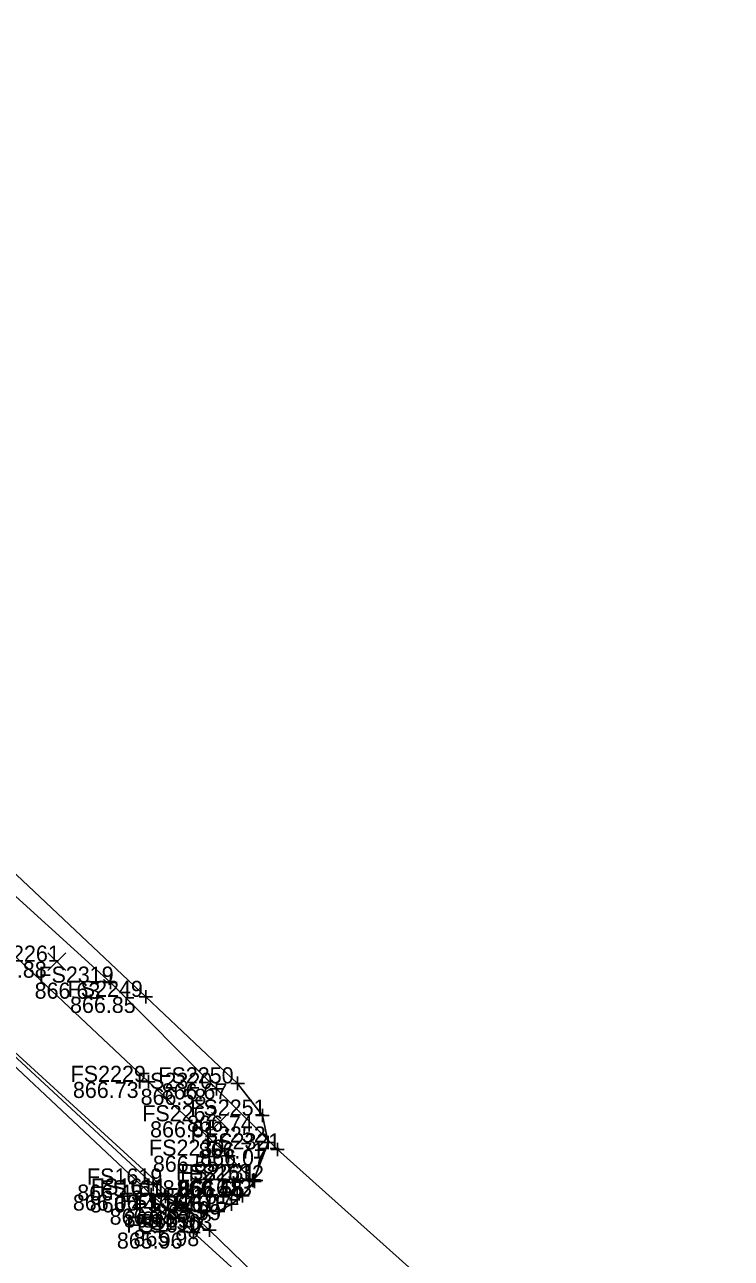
# Model space of a CAD drawing. Extents: x 1479420 to 1479833, y 379731 to 380103.
# Drawn here: x 1479766 to 1479818.8, y 379820.1 to 379912.2 of the extents above; entities that cross this region are included whole.
import ezdxf

# ---------------------------------------------------------------- set-up
doc = ezdxf.new("R2010")
doc.units = 0
for name, color, linetype in [('PV_X_Curb', 7, 'Continuous'), ('PV_X_Walk', 7, 'Continuous'), ('SV_X_Random_Point', 7, 'Continuous'), ('SV_X_Shot_Marker', 7, 'Continuous'), ('SV_X_Text_Elevation', 7, 'Continuous'), ('SV_X_Text_Name', 7, 'Continuous'), ('UT_X_Gas', 7, 'Continuous'), ('UT_X_Water', 7, 'Continuous')]:
    doc.layers.add(name, color=color, linetype=linetype)

msp = doc.modelspace()

# ---------------------------------------------------------------- linework, layer by layer
at = {"layer": 'PV_X_Curb'}
for points in [[(1479714.573, 379931.716), (1479714.771, 379922.599), (1479714.229, 379900.013), (1479714.491, 379898.192), (1479715.218, 379896.002), (1479717.036, 379893.796), (1479731.944, 379880.013), (1479745.709, 379867.308), (1479763.187, 379850.751), (1479775.061, 379839.578), (1479781.928, 379833.121), (1479783.777, 379830.713), (1479784.214, 379828.705), (1479783.141, 379825.906)], [(1479818.811, 379784.125), (1479817.439, 379785.583), (1479804.233, 379798.167), (1479791.741, 379810.033), (1479778.638, 379821.983), (1479775.464, 379824.819), (1479758.378, 379840.845), (1479740.8, 379857.042), (1479740.592, 379857.626), (1479737.808, 379860.038), (1479735.87, 379861.852), (1479733.787, 379863.763), (1479718.701, 379877.898), (1479705.478, 379890.334), (1479700.95, 379894.575), (1479699.048, 379897.264), (1479697.778, 379899.5), (1479696.445, 379902.732), (1479695.776, 379905.397), (1479695.475, 379907.419), (1479695.142, 379911.53), (1479695.083, 379915.321)], [(1479783.191, 379825.805), (1479782.298, 379824.723), (1479781.461, 379824.102), (1479780.469, 379823.552), (1479779.204, 379823.559), (1479778.041, 379823.771), (1479776.54, 379824.685), (1479775.613, 379825.569), (1479758.651, 379841.237), (1479741.143, 379857.755), (1479738.162, 379860.576), (1479738.292, 379860.892), (1479733.926, 379864.875), (1479733.77, 379864.743), (1479718.903, 379878.446), (1479705.833, 379890.72), (1479701.383, 379894.844), (1479699.526, 379897.551), (1479698.177, 379899.762), (1479696.913, 379902.812), (1479696.188, 379905.546), (1479696.149, 379907.481), (1479695.686, 379911.644), (1479695.62, 379915.117)]]:
    msp.add_lwpolyline(points, dxfattribs=at)
at = {"layer": 'PV_X_Walk'}
msp.add_lwpolyline([(1479714.407, 379931.65), (1479709.589, 379929.394), (1479706.362, 379927.006), (1479703.827, 379924.359), (1479702.38, 379922.179), (1479701.604, 379920.676), (1479701.232, 379918.285), (1479701.216, 379916.698), (1479701.871, 379912.679), (1479703.861, 379906.887), (1479705.425, 379903.147), (1479707.313, 379899.269), (1479709.707, 379895.256), (1479713.76, 379890.533), (1479726.083, 379878.959), (1479737.973, 379867.989), (1479746.242, 379860.487), (1479749.391, 379863.573), (1479751.936, 379861.299), (1479749.037, 379858.043), (1479762.483, 379845.218), (1479775.26, 379833.23), (1479781.252, 379827.717), (1479783.036, 379825.875)], dxfattribs=at)
at = {"layer": 'SV_X_Random_Point'}
for p, q in [((1479767.756, 379841.539), (1479769.09, 379842.874)), ((1479767.756, 379842.874), (1479769.09, 379841.539)), ((1479779.963, 379829.621), (1479781.297, 379830.956)), ((1479779.963, 379830.956), (1479781.297, 379829.621))]:
    msp.add_line(p, q, dxfattribs=at)
at = {"layer": 'SV_X_Shot_Marker'}
for p, q in [((1479771.936, 379840.641), (1479772.936, 379840.641)), ((1479772.436, 379841.141), (1479772.436, 379840.141)), ((1479772.436, 379840.641), (1479772.436, 379840.641)), ((1479774.561, 379839.578), (1479775.561, 379839.578)), ((1479775.061, 379840.078), (1479775.061, 379839.078)), ((1479775.061, 379839.578), (1479775.061, 379839.578)), ((1479774.76, 379833.23), (1479775.76, 379833.23)), ((1479775.26, 379833.73), (1479775.26, 379832.73)), ((1479775.26, 379833.23), (1479775.26, 379833.23)), ((1479780.346, 379833.215), (1479780.346, 379832.215)), ((1479781.428, 379833.121), (1479782.428, 379833.121)), ((1479781.928, 379833.621), (1479781.928, 379832.621)), ((1479781.928, 379833.121), (1479781.928, 379833.121)), ((1479779.846, 379832.715), (1479780.846, 379832.715)), ((1479780.346, 379832.715), (1479780.346, 379832.715)), ((1479783.777, 379831.213), (1479783.777, 379830.213)), ((1479783.277, 379830.713), (1479784.277, 379830.713)), ((1479783.777, 379830.713), (1479783.777, 379830.713)), ((1479783.714, 379828.705), (1479784.714, 379828.705)), ((1479784.214, 379829.205), (1479784.214, 379828.205)), ((1479784.214, 379828.705), (1479784.214, 379828.705)), ((1479784.901, 379828.691), (1479784.901, 379827.691)), ((1479780.752, 379827.717), (1479781.752, 379827.717)), ((1479781.252, 379828.217), (1479781.252, 379827.217)), ((1479781.252, 379827.717), (1479781.252, 379827.717)), ((1479784.401, 379828.191), (1479785.401, 379828.191)), ((1479784.901, 379828.191), (1479784.901, 379828.191)), ((1479775.613, 379826.069), (1479775.613, 379825.069)), ((1479782.536, 379825.875), (1479783.536, 379825.875)), ((1479782.641, 379825.906), (1479783.641, 379825.906)), ((1479782.691, 379825.805), (1479783.691, 379825.805)), ((1479783.036, 379826.375), (1479783.036, 379825.375)), ((1479783.036, 379825.875), (1479783.036, 379825.875)), ((1479783.141, 379826.406), (1479783.141, 379825.406)), ((1479783.141, 379825.906), (1479783.141, 379825.906)), ((1479783.191, 379826.305), (1479783.191, 379825.305)), ((1479783.191, 379825.805), (1479783.191, 379825.805)), ((1479774.964, 379824.819), (1479775.964, 379824.819)), ((1479775.113, 379825.569), (1479776.113, 379825.569)), ((1479775.464, 379825.319), (1479775.464, 379824.319)), ((1479775.464, 379824.819), (1479775.464, 379824.819)), ((1479775.613, 379825.569), (1479775.613, 379825.569)), ((1479776.54, 379825.185), (1479776.54, 379824.185)), ((1479782.298, 379825.223), (1479782.298, 379824.223)), ((1479776.04, 379824.685), (1479777.04, 379824.685)), ((1479776.54, 379824.685), (1479776.54, 379824.685)), ((1479778.041, 379824.271), (1479778.041, 379823.271)), ((1479779.204, 379824.059), (1479779.204, 379823.059)), ((1479780.469, 379824.052), (1479780.469, 379823.052)), ((1479780.961, 379824.102), (1479781.961, 379824.102)), ((1479781.461, 379824.602), (1479781.461, 379823.602)), ((1479781.461, 379824.102), (1479781.461, 379824.102)), ((1479781.798, 379824.723), (1479782.798, 379824.723)), ((1479782.298, 379824.723), (1479782.298, 379824.723)), ((1479777.541, 379823.771), (1479778.541, 379823.771)), ((1479778.041, 379823.771), (1479778.041, 379823.771)), ((1479778.704, 379823.559), (1479779.704, 379823.559)), ((1479779.204, 379823.559), (1479779.204, 379823.559)), ((1479779.969, 379823.552), (1479780.969, 379823.552)), ((1479780.469, 379823.552), (1479780.469, 379823.552)), ((1479778.138, 379821.983), (1479779.138, 379821.983)), ((1479778.638, 379822.483), (1479778.638, 379821.483)), ((1479778.638, 379821.983), (1479778.638, 379821.983)), ((1479779.315, 379822.167), (1479780.315, 379822.167)), ((1479779.815, 379822.667), (1479779.815, 379821.667)), ((1479779.815, 379822.167), (1479779.815, 379822.167))]:
    msp.add_line(p, q, dxfattribs=at)
at = {"layer": 'UT_X_Gas'}
msp.add_lwpolyline([(1479667.444, 379946.572), (1479666.862, 379942.802), (1479667.538, 379940.507), (1479675.403, 379934.504), (1479682.743, 379926.326), (1479692.421, 379916.824), (1479702.659, 379906.694), (1479713.881, 379895.567), (1479724.225, 379885.781), (1479733.117, 379877.795), (1479742.697, 379869.326), (1479754.816, 379857.131), (1479762.869, 379849.318), (1479772.436, 379840.641), (1479780.346, 379832.715), (1479784.901, 379828.191), (1479795.906, 379818.324), (1479806.128, 379806.719), (1479816.671, 379794.927)], dxfattribs=at)
at = {"layer": 'UT_X_Water'}
msp.add_lwpolyline([(1479682.752, 379913.809), (1479688.353, 379908.314), (1479695.924, 379900.161), (1479705.441, 379891.596), (1479719.261, 379878.171), (1479726.79, 379870.913), (1479729.608, 379870.544), (1479735.551, 379869.684), (1479739.947, 379866.49), (1479744.65, 379861.847), (1479745.833, 379856.023), (1479753.929, 379847.124), (1479764.701, 379835.97), (1479779.815, 379822.167), (1479798.248, 379804.283), (1479815.468, 379787.444)], dxfattribs=at)

# ---------------------------------------------------------------- texts
at = {"layer": 'SV_X_Text_Elevation'}
for s, p in [('866.88', (1479762.754, 379841.007)), ('866.63', (1479766.758, 379839.441)), ('866.85', (1479769.402, 379838.378)), ('866.73', (1479769.619, 379832.03)), ('866.67', (1479776.25, 379831.921)), ('866.58', (1479774.677, 379831.515)), ('866.61', (1479775.385, 379829.089)), ('866.74', (1479778.146, 379829.513)), ('866.71', (1479779.007, 379827.505)), ('866.55', (1479775.593, 379826.517)), ('866.07', (1479779.128, 379826.991)), ('866.48', (1479777.358, 379824.675)), ('866.55', (1479777.482, 379824.706)), ('866.55', (1479777.532, 379824.605)), ('866.06', (1479769.616, 379823.619)), ('866.45', (1479769.944, 379824.369)), ('866.07', (1479776.525, 379823.523)), ('866.44', (1479770.881, 379823.485)), ('865.99', (1479775.792, 379822.902)), ('866.35', (1479772.363, 379822.571)), ('866.09', (1479773.422, 379822.359)), ('865.97', (1479774.81, 379822.352)), ('865.96', (1479772.903, 379820.783)), ('865.98', (1479774.146, 379820.967))]:
    msp.add_text(s, height=1.2, dxfattribs=at).set_placement(p)
at = {"layer": 'SV_X_Text_Name'}
for s, p in [('FS2261', (1479763.018, 379842.207)), ('FS2319', (1479767.042, 379840.641)), ('FS2249', (1479769.222, 379839.578)), ('FS2229', (1479769.449, 379833.23)), ('FS2250', (1479776.004, 379833.121)), ('FS2320', (1479774.403, 379832.715)), ('FS2262', (1479774.801, 379830.289)), ('FS2251', (1479778.391, 379830.713)), ('FS2252', (1479778.403, 379828.705)), ('FS2321', (1479779.496, 379828.191)), ('FS2230', (1479775.309, 379827.717)), ('FS1619', (1479770.673, 379825.569)), ('FS2253', (1479777.321, 379825.906)), ('FS2231', (1479777.631, 379825.875)), ('FS1612', (1479778.27, 379825.805)), ('FS1611', (1479770.967, 379824.819)), ('FS1618', (1479771.6, 379824.685)), ('FS1613', (1479777.367, 379824.723)), ('FS1617', (1479773.11, 379823.771)), ('FS1616', (1479774.198, 379823.559)), ('FS1615', (1479775.538, 379823.552)), ('FS1614', (1479776.54, 379824.102)), ('FS1610', (1479773.603, 379821.983)), ('FS1563', (1479774.411, 379822.167))]:
    msp.add_text(s, height=1.2, dxfattribs=at).set_placement(p)

doc.saveas('drawing.dxf')
